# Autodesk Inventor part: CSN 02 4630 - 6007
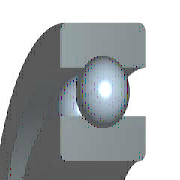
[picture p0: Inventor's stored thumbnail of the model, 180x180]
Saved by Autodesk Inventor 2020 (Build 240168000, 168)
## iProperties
Created: 2019-01
Part Number: CSN 02 4630 - 6007
Material: Ocel, měkká
Description: Kuličková ložiska jednořadá
Document SubType Name: Modeling
Standard: CSN 02 4630
Designer: doma
Standards Organization: CSN
Language: cs-CZ
Size Designation: 6007
Categories: <MemberInstance><Categories><Category DisplayName="Součásti hřídele" InternalName="7f7aeb1f-a693-4053-b835-cee3144e0d98" Mnemonic="SHFT"><Category DisplayName="
Density: 7.85 g/cm^3
Appearance: Pololeštěná
Mass: 151.975 g
Surface Area: 128.586 cm^2
Volume: 19.3598 cm^3
IsCustomPart: 0
Author: doma
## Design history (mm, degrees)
sketch "Náčrt" dims "d0" = 7.02 (= -0.26 x WD + 0.26 x BD)
  geometry: L1 (3.49, 24.25)-(10.51, 24.25); L2 (7, 24.25)-(7, 20.74); L3 (7, 24.25)-(7, 27.76); L4 (4.392, 21.901)-(0, 21.901); L5 (0, 17.5)-(14, 17.5); L6 (4.392, 26.599)-(0, 26.599); L7 (0, 31)-(14, 31); L8 (14, 17.5)-(14, 21.901); L9 (9.608, 21.901)-(14, 21.901); L10 (9.608, 26.599)-(14, 26.599); L11 (14, 31)-(14, 26.599); L12 (-1.4, 0)-(8.4, 0) reference; L13 (0, -0.3)-(0, 5.3) reference
  constraints: 22 end point, 4 point on line, 2 collinear, 2 perpendicular, 2 symmetric about line, 1 midpoint, 1 parallel, 14 other
  dimensions: "d9" = 35 diameter of L5 L12 (= WD); "d11" = 62 diameter of L7 L12 (= BD); "d12" = 14 distance between parallel lines of L8 L13 (= KB); "d13" = 43.802 diameter of L9 L12 (= 0.326 x BD + 0.674 x WD)
revolve "Těleso" stored, may be unused: angle "d6" = 90 deg
revolve "Kulička" stored, may be unused: angle "d7" = 90 deg
pattern_circular "Kuličky" dims angle "d3" = 360 deg
body "Solid1"
fillet "Zaoblení1" dims "d1" = 1 (= KRS)
other parameters: "WD" = 35 [user parameter; used in 5 equation terms], "BD" = 62 [user parameter; used in 5 equation terms], "KB" = 14 [user parameter; used in 1 equation term], "KRS" = 1 [user parameter; used in 1 equation term], "d4" = 0, "d5" = 0, "d8" = 0, "d14" = 0, "d15" = 0, "BBA" = 0 [user parameter], "BC0" = 1.02e+07 [user parameter], "BC" = 1.59e+07 [user parameter], "BR" = 31 (= 0.5 x BD) [user parameter], "WR" = 17.5 (= 0.5 x WD) [user parameter]
